Omron CX-Programmer project NewProject (CX-Programmer 7.03)

# PLC NewPLC1: CJ1M CPU22
I/O table (CPU CJ1M-CPU22): rack 0 slot 0 CJ1W-MAD42; rack 0 slot 1 CJ1W-ID211; rack 0 slot 2 CJ1W-OD212; rack 0 slot 3 CJ1W-ID261

## Program NewProgram1 (cyclic task 0)

### Section Section1

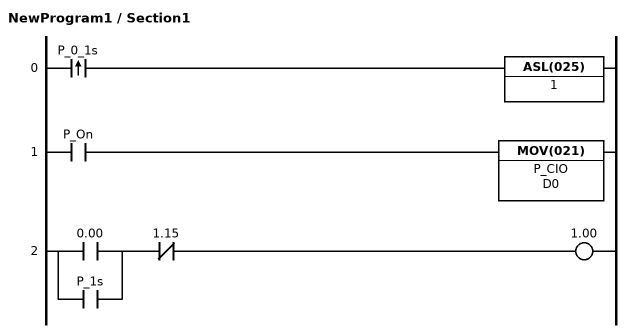
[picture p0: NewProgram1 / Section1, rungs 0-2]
; rung 0
@LD P_0_1s
ASL(025) 1
; rung 1
LD P_On
MOV(021) P_CIO D0
; rung 2
LD 0.00
OR P_1s
ANDNOT 1.15
OUT 1.00
; rung 3
END(001)

### Section Section2
; rung 0
END(001)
